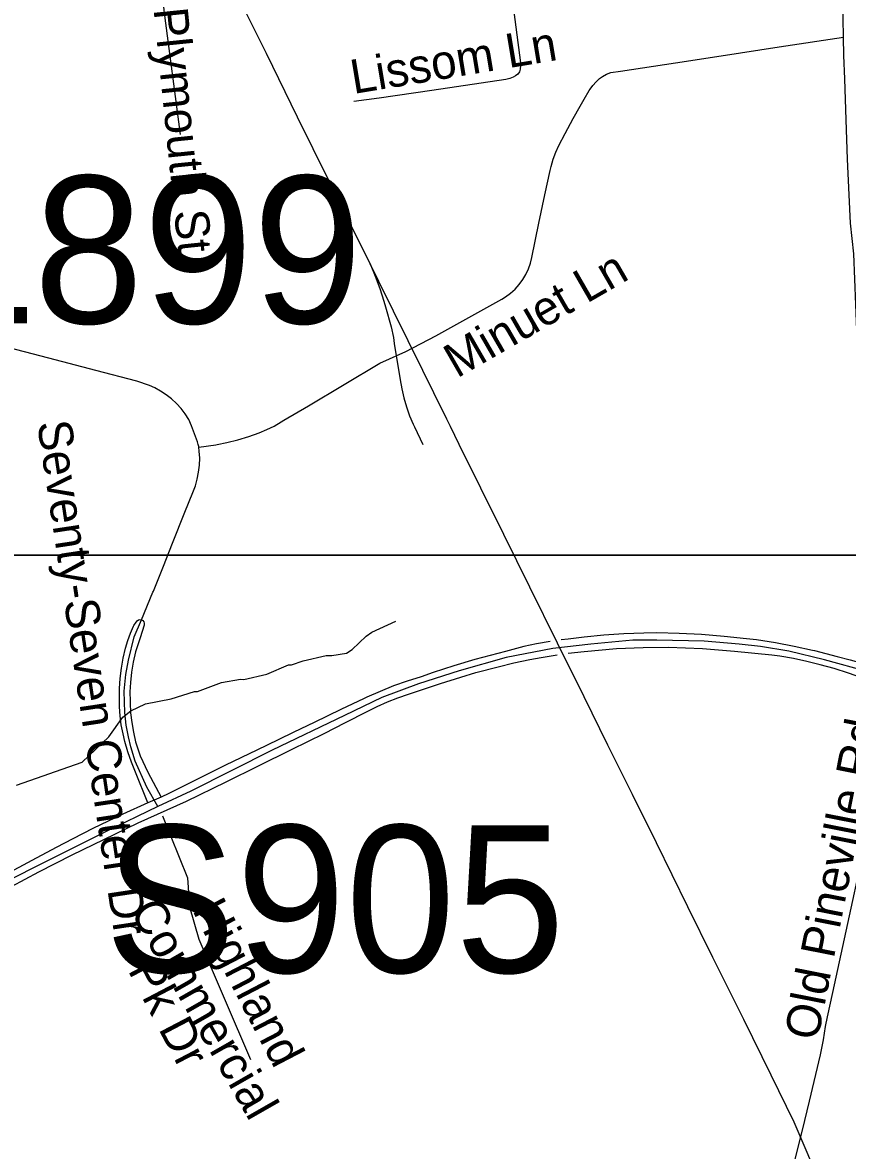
# Model space of a CAD drawing. Extents: x 1383679 to 1536984, y 460658 to 651027.
# Drawn here: x 1436512 to 1438807, y 519102 to 522240 of the extents above; entities that cross this region are included whole.
import ezdxf

# ---------------------------------------------------------------- set-up
doc = ezdxf.new("R2010")
doc.units = 0
for name, color, linetype in [('Exist Hydrographic Misc Water Feature', 7, 'Continuous'), ('Exist Railroad Mainline', 7, 'Continuous'), ('Exist Railroad Spur', 7, 'Continuous'), ('Exist Road Non-System Type 51', 7, 'Continuous'), ('Exist Road Non-System Type 51 Label', 7, 'Continuous'), ('Exist Road Primary Interstate Structure Cantilever Sign Number Label', 7, 'Continuous'), ('Exist Road Primary Interstate Structure Ovrhead Sign Number Label', 7, 'Continuous'), ('Map Preparation Inset Cut Line', 7, 'Continuous')]:
    doc.layers.add(name, color=color, linetype=linetype)

msp = doc.modelspace()

# ---------------------------------------------------------------- linework, layer by layer
at = {"layer": 'Exist Hydrographic Misc Water Feature'}
msp.add_lwpolyline([(1436494.8, 520118.7), (1436678.2, 520182.6), (1436751.8, 520252.9), (1436790.9, 520308), (1436813.4, 520325.5), (1436853.8, 520344.5), (1436925.7, 520358.2), (1436990.5, 520379.4), (1436998.5, 520379.3), (1437065.2, 520403.6), (1437118.5, 520413.6), (1437127.3, 520412.3), (1437191.6, 520426.9), (1437252.2, 520453.6), (1437260.2, 520453.4), (1437292.5, 520464.6), (1437356.8, 520479.2), (1437372.8, 520478.8), (1437413, 520485.9), (1437429.2, 520495.5), (1437468, 520532.7), (1437484.2, 520544.3), (1437550.8, 520574.8)], dxfattribs=at)
at = {"layer": 'Exist Railroad Mainline'}
for points in [[(1437479.3, 521568.3), (1437408.7, 521710.5), (1437276.9, 521976.9), (1437190.4, 522153.6), (1437095, 522345.6), (1436954.4, 522629.6), (1436844.6, 522851.7), (1436715.4, 523112.7)], [(1438825.2, 518766.8), (1438785.7, 518877.6), (1438739.2, 518994.9), (1438658.8, 519180.8), (1438595.1, 519312), (1438518.9, 519466.5), (1438433.3, 519638.7), (1438363.7, 519780.4), (1438275.9, 519957.6), (1438209, 520092.4), (1438141, 520230), (1438075, 520364.6), (1438000.9, 520513.3), (1437924, 520669.5), (1437851.4, 520815.7), (1437787, 520944.9), (1437727.4, 521066), (1437703, 521115.8), (1437692.7, 521136.9), (1437656.6, 521209.4), (1437625.4, 521272.1), (1437503.5, 521519.5), (1437479.3, 521568.3)]]:
    msp.add_lwpolyline(points, dxfattribs=at)
at = {"layer": 'Exist Railroad Spur'}
msp.add_lwpolyline([(1437479.3, 521568.3), (1437493.5, 521534.2), (1437506.3, 521499.5), (1437517.6, 521464.3), (1437522.1, 521448.6), (1437537.9, 521393.7), (1437543.9, 521363.5), (1437546.5, 521347.4), (1437562.9, 521246.2), (1437567.1, 521220.7), (1437572.9, 521195.4), (1437580.2, 521170.5), (1437589, 521146.1), (1437599.3, 521122.3), (1437602.7, 521115.3), (1437626.2, 521066)], dxfattribs=at)
at = {"layer": 'Exist Road Non-System Type 51'}
msp.add_line((1436897.7, 520085.4), (1436860.6, 520068.9), dxfattribs=at)
for points in [[(1438796.3, 522199.2), (1438795.6, 522251), (1438794.9, 522300.5), (1438792.7, 522350), (1438789.3, 522394.6), (1438782.3, 522451.2), (1438773.7, 522507.5), (1438763.5, 522563.6), (1438758.9, 522586.3), (1438754, 522606.2)], [(1437853.6, 522461.7), (1437897.7, 522127.5), (1437897.7, 522120.6), (1437896.9, 522110), (1437894.7, 522102.5), (1437890, 522096.4), (1437883.9, 522091.7), (1437877.2, 522088.1), (1437868, 522084.2), (1437856.6, 522081.1), (1437650.6, 522050.4), (1437504.8, 522028.9), (1437433.4, 522019.7)], [(1436901.5, 522323.9), (1436905.2, 522273.3), (1436950.4, 521928.1)], [(1437002.4, 521058.5), (1437050, 521065.4), (1437053.3, 521066), (1437080.8, 521071.4), (1437111.2, 521078.9), (1437141.3, 521088), (1437170.8, 521098.6), (1437191.8, 521107.3), (1437212.1, 521117.4), (1437231.7, 521129), (1437239.4, 521134), (1437308, 521173.9), (1437506.2, 521292.7), (1437578.1, 521324.4), (1437661.7, 521368.7), (1437845.4, 521470), (1437855.8, 521476.4), (1437869.7, 521486.6), (1437882.5, 521498.2), (1437894, 521511.1), (1437904.1, 521525), (1437912.7, 521539.3), (1437919.8, 521554.7), (1437925.3, 521570.6), (1437928.8, 521586.3), (1437948.7, 521681.6), (1437965.8, 521760.5), (1437980.4, 521828.1), (1437982.9, 521839.1), (1437988.7, 521859.3), (1437995.9, 521878.8), (1438004.4, 521897.9), (1438022.4, 521931.3), (1438043.8, 521972.5), (1438063.3, 522007.4), (1438075, 522027), (1438089.1, 522050.7), (1438091.2, 522054), (1438099.1, 522065), (1438107.9, 522074.9), (1438117.7, 522083.8), (1438126, 522089.7), (1438136.6, 522095.8), (1438148.8, 522100.3), (1438176.1, 522104.6), (1438359.7, 522131.8), (1438510.1, 522155), (1438617.7, 522171.7), (1438796.3, 522199.2)], [(1438863.7, 520592.3), (1438859.7, 520687.3), (1438854.2, 520789.3), (1438848.1, 520898.5), (1438848.7, 520985.9), (1438847.9, 521066), (1438847.8, 521070.5), (1438840.5, 521218.3), (1438831, 521455.1), (1438825.7, 521596.7), (1438815.6, 521681.7), (1438812.5, 521760.1), (1438807.7, 521859.4), (1438804, 521968.9), (1438800, 522083.1), (1438797.1, 522148), (1438796.3, 522199.2)], [(1437002.4, 521058.5), (1437002.1, 521060.5), (1437000.6, 521066), (1436998.7, 521073.5), (1436981.8, 521118), (1436974.8, 521135.3), (1436964.7, 521151.2), (1436953.2, 521166.1), (1436940.5, 521180), (1436926.8, 521192.8), (1436912, 521204.5), (1436896.2, 521214.8), (1436879.7, 521223.8), (1436865.2, 521230.2), (1436829.6, 521242.1), (1436715.7, 521271.8), (1436585.5, 521306), (1436448.9, 521341.4)], [(1436876.1, 520658.3), (1436903.9, 520727.5), (1436929.5, 520792), (1436963.6, 520878.2), (1436986.1, 520932.6), (1436992.9, 520950.9), (1436998.2, 520969.7), (1437002, 520988.8), (1437004.2, 521008.2), (1437004.9, 521027.7), (1437003.9, 521047.2), (1437002.4, 521058.5)], [(1436843, 520578.1), (1436874.9, 520655.4), (1436876.1, 520658.3)], [(1436860.6, 520068.9), (1436826.4, 520154.7), (1436815, 520182.7), (1436805.1, 520211.2), (1436796.7, 520240.2), (1436791.7, 520260.8), (1436786.8, 520285.9), (1436783.4, 520311.2), (1436781.6, 520336.8), (1436781.4, 520358.8), (1436781.7, 520387.2), (1436783.5, 520415.6), (1436787, 520443.9), (1436791.9, 520471.8), (1436798.5, 520499.4), (1436804.5, 520520.5), (1436812.1, 520541), (1436821.1, 520561), (1436821.8, 520562.5), (1436828.1, 520572.2), (1436830.6, 520575.7), (1436834.2, 520578), (1436838.4, 520578.9), (1436842.6, 520578.3), (1436843, 520578.1)], [(1436888.3, 520058.8), (1436858, 520113.1), (1436825.6, 520185), (1436813.5, 520225.5), (1436806.8, 520252.9), (1436800.1, 520284.9), (1436796.7, 520320.2), (1436795, 520380.3), (1436799, 520426.7), (1436806.4, 520466.6), (1436822.9, 520530.6), (1436843, 520578.1)], [(1436843, 520578.1), (1436846.4, 520576.1), (1436849.1, 520572.8), (1436850.5, 520568.7), (1436850.3, 520564.4), (1436850.1, 520563.7), (1436838.8, 520528.7), (1436826.4, 520489.2), (1436820.1, 520461), (1436815.4, 520432.6), (1436812.3, 520404), (1436810.9, 520377.9), (1436811.1, 520351.8), (1436811.3, 520347.2), (1436812.7, 520320), (1436815.8, 520292.9), (1436820.4, 520266), (1436826.5, 520239.4), (1436832.4, 520219.6), (1436839.7, 520200.4), (1436860.2, 520154.5), (1436897.7, 520085.4)], [(1438011.2, 520523.2), (1438030.2, 520525.9), (1438074.6, 520530.8), (1438075, 520530.8), (1438129.8, 520536.3), (1438185, 520540.2), (1438240.4, 520542.6), (1438276.6, 520543.2), (1438339.2, 520541.5), (1438401.7, 520538.2), (1438464.1, 520533.3), (1438526.4, 520526.8), (1438554.5, 520523.3), (1438606.8, 520515.1), (1438658.8, 520505.3), (1438710.5, 520493.9), (1438715.5, 520492.8), (1438778.4, 520476.7), (1438815, 520467.4), (1438851.3, 520456.6), (1438862.5, 520452.8)], [(1438865.1, 520433.3), (1438743.2, 520467.3), (1438644.2, 520490.8), (1438565.5, 520503.9), (1438506.2, 520511), (1438408.9, 520518.9), (1438276.9, 520521.5), (1438210.6, 520521.5), (1438093.4, 520511), (1437988, 520498.6), (1437857.3, 520473.8), (1437727, 520436.5), (1437613.9, 520400), (1437511.9, 520362.7), (1437408.2, 520312.4), (1437206.8, 520215.7), (1436980.2, 520102), (1436888.3, 520058.8)], [(1437979.9, 520518.4), (1437942, 520511.5), (1437906.6, 520503.9), (1437855.5, 520490.4), (1437770.8, 520467.6), (1437712.3, 520450.3), (1437654.3, 520431.4), (1437621.2, 520419.9), (1437582.6, 520407.9), (1437544.5, 520394.3), (1437507, 520379.3), (1437470.1, 520362.9), (1437462.4, 520359.2), (1437397.5, 520328.9), (1437323.2, 520292.9), (1437267, 520265.9), (1437223.7, 520244.6), (1437163.7, 520216.1), (1437076.6, 520173.8), (1436919.3, 520095.1), (1436897.7, 520085.4)], [(1438865.5, 520410.4), (1438850.5, 520416.5), (1438810.7, 520430.3), (1438770.3, 520442.6), (1438731.9, 520452.9), (1438694.6, 520462.5), (1438656.9, 520470.6), (1438618.9, 520477.1), (1438597, 520480.2), (1438493.3, 520490.4), (1438404.4, 520497.6), (1438309.4, 520501.6), (1438239.3, 520500.4), (1438165.1, 520497.5), (1438075, 520489.5), (1438074.8, 520489.5), (1438030.3, 520484.6)], [(1436481.1, 519836.2), (1436557.3, 519877.8), (1436650.4, 519924.3), (1436768.8, 519981.9), (1436833.6, 520013.4), (1436967.9, 520074.1), (1437079, 520127.3), (1437168.7, 520171.8), (1437260.5, 520217.5), (1437350.9, 520262.1), (1437410.7, 520293), (1437471, 520323.4), (1437498.8, 520337.6), (1437527.3, 520350.4), (1437556.4, 520361.6), (1437586, 520371.4), (1437675.1, 520401.2), (1437731.9, 520419.3), (1437773.6, 520432.1), (1437835.7, 520447.6), (1437879.5, 520458.5), (1437923.6, 520467.8), (1437955, 520473.4), (1437999.5, 520480.6)], [(1438865.5, 520410.4), (1438869.8, 520277.1), (1438873.2, 520169.3), (1438875, 520115.7), (1438868.7, 520057.4), (1438857.9, 519979.5), (1438838.5, 519874.5), (1438816.8, 519776), (1438788.9, 519648.1), (1438766, 519541.3), (1438751, 519474.2), (1438745.7, 519447.1), (1438740.2, 519410.4), (1438731.1, 519368.1), (1438701.2, 519239.8), (1438681.9, 519158.9), (1438661.3, 519077.9), (1438651.5, 519049.7), (1438643.2, 519022.9), (1438634.9, 518985.8), (1438628.1, 518948.3), (1438625.3, 518927.9)], [(1436860.6, 520068.9), (1436791.3, 520037.9), (1436707.5, 519997.7), (1436652, 519969.4), (1436605.2, 519945.3), (1436538, 519909.1), (1436464, 519869.3), (1436403.6, 519837.1), (1436342.4, 519806.3), (1436321, 519795.9), (1436245.4, 519759.8), (1436168.2, 519722.3), (1436085.9, 519679.6), (1436082.1, 519675.5), (1436079.7, 519670.6), (1436078.7, 519665.2), (1436079.3, 519659.8), (1436080, 519658.2)], [(1436888.3, 520058.8), (1436742.8, 519988.3), (1436535.1, 519884.4), (1436342.8, 519786.4), (1436135, 519683.1), (1436080, 519658.2)], [(1436901.8, 520033.4), (1436970.9, 519860.4), (1436976.7, 519779.7), (1437002.6, 519690.3), (1437146.7, 519355.8)]]:
    msp.add_lwpolyline(points, dxfattribs=at)
at = {"layer": 'Map Preparation Inset Cut Line'}
for points in [[(1458567.8, 520758.2), (1396051.8, 520758.2), (1396051.8, 564142.2), (1458567.8, 564142.2), (1458567.8, 520758.2)], [(1446195.4, 477316), (1383679.3, 477316), (1383679.3, 520758.2), (1458567.8, 520758.2), (1458567.8, 493672.2), (1446195.4, 493672.2), (1446195.4, 477316)]]:
    msp.add_lwpolyline(points, dxfattribs=at)

# ---------------------------------------------------------------- texts
at = {"layer": 'Exist Road Non-System Type 51 Label'}
for s, rotation, p in [('Plymouth St', 275.8064, (1436876.4, 522277.1)), ('Lissom Ln', 9.4632, (1437432.9, 522040.8)), ('Minuet Ln', 29.9751, (1437720.9, 521249.1)), ('Seventy-Seven Center Dr', 278.5786, (1436552.2, 521126.4)), ('Old Pineville Rd', 78.8799, (1438724.4, 519405.3)), ('Highland', 297.4744, (1436983.1, 519771.3)), ('Commercial', 299.7448, (1436809, 519768.3)), ('Pk Dr', 297.6459, (1436803.7, 519604.1))]:
    msp.add_text(s, height=95, rotation=rotation, dxfattribs=at).set_placement(p)
at = {"layer": 'Exist Road Primary Interstate Structure Cantilever Sign Number Label'}
msp.add_text('L899', height=410.1, dxfattribs=at).set_placement((1436237.9, 521403))
at = {"layer": 'Exist Road Primary Interstate Structure Ovrhead Sign Number Label'}
msp.add_text('S905', height=410.1, dxfattribs=at).set_placement((1436740.4, 519597))

doc.saveas('drawing.dxf')
